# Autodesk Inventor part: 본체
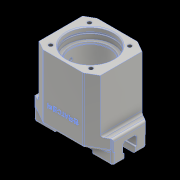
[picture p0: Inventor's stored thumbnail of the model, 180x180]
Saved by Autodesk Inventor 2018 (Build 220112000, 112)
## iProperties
Created: 2023-05
Part Number: 본체
Material: 알루미늄 6061
Document SubType Name: Modeling
Designer: home
Density: 2.7 g/cm^3
Appearance: 알루미늄 - 평지
Mass: 915.939 g
Surface Area: 565.433 cm^2
Volume: 339.237 cm^3
Author: home
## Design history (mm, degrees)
sketch "스케치1"
  geometry: L1 (-26, -35)-(26, -35); L2 (40, -26.917)-(40, 26.917); L3 (26, 35)-(-26, 35); L4 (-40, 26.917)-(-40, -26.917); L5 (-40, -35)-(40, 35); L6 (40, -35)-(-40, 35); L7 (-26, 35)-(-51, 20.566); L8 (26, 35)-(51, 20.566); L9 (-26, -35)-(-51, -20.566); L10 (26, -35)-(51, -20.566); L11 (51, -20)-(51, 20); L12 (-51, -20)-(-51, 20); 5 further points
  constraints: 24 end point, 8 point on line, 6 midpoint, 2 horizontal alignment, 2 parallel, 2 vertical, 1 horizontal, 1 perpendicular
  dimensions: "d0" = 80 distance between parallel lines of L2 L4; "d1" = 70 distance between parallel lines of L1 L3; "d4" = 52 distance of L3.end L3.start; "d5" = 52 distance of L1.end L1.start; "d6" = 26 horizontal distance of L1.start point (0, 0); "d7" = 26 horizontal distance of L3.end point (0, 0); "d8" = 60 deg angle of L7 L9; "d9" = 30 deg angle of L1 L9; "d10" = 60 deg angle of L8 L10; "d11" = 30 deg angle of L1 L10; "d12" = 71.1859 deg angle of L5 L8; "d13" = 11.1859 deg angle of L6 L8; "d14" = 43.31089 distance from line of point (0, 0) L8; "d15" = 40 distance from line of point (0, 0) L2; "d16" = 7 distance from line of L5.end L8; "d17" = 53.62178 distance from line of L6.start L8; "d18" = 33 distance from line of L6.end L8; "d19" = 93.62178 distance from line of L5.start L8; "d120" = 40 distance of L11.start L11.end; "d121" = 40 distance of L12.start L12.end; "d122" = 102 distance between parallel lines of L12 L11; "d123" = 51 distance from line of point (0, 0) L11
extrude "돌출1" new body sketch "스케치1" distance "d20" = 84; taper "d21" = 0 deg
sketch "스케치4"
  geometry: L1 (51, -69)-(-51, -69); L2 (-51, -69)-(-51, -99); L3 (-51, -99)-(51, -99); L4 (51, -99)-(51, -69); L5 (51, -69)-(-51, -99); L6 (-51, -69)-(51, -99); 3 further points
  constraints: 12 end point, 3 midpoint, 2 parallel, 1 horizontal, 1 perpendicular, 1 vertical alignment
  dimensions: "d23" = 102 distance between parallel lines of L2 L4; "d24" = 99 distance from line of point (0, 0) L3; "d25" = 30 distance between parallel lines of L3 L1
extrude "돌출2" join sketch "스케치4" stored distance "d26" = 44; taper "d27" = 0 deg
sketch "스케치5"
  geometry: L1 (-51, -99)-(-51, -69) reference; L2 (-51, -69)-(-40, -69) reference; L3 (-40, -84)-(-40, -69) reference; L4 (40, -84)-(-40, -84) reference; L5 (40, -69)-(40, -84) reference; L6 (40, 0)-(40, -69) reference; L7 (-40, 0)-(40, 0) reference; L8 (-40, -69)-(-40, 0) reference; L9 (51, -99)-(-51, -99) reference; L10 (51, -69)-(51, -99) reference; L11 (40, -69)-(51, -69) reference; L12 (25, -93)-(-25, -93); L13 (-25, -93)-(-25, -99); L14 (-25, -99)-(25, -99); L15 (25, -99)-(25, -93); L16 (25, -93)-(-25, -99); L17 (-25, -93)-(25, -99); 5 further points
  constraints: 12 end point, 6 midpoint, 2 parallel, 1 horizontal, 1 perpendicular, 1 vertical alignment
  dimensions: "d28" = 50 distance between parallel lines of L13 L15; "d29" = 6 distance between parallel lines of L12 L14
extrude "돌출3" cut sketch "스케치5" extent not by distance; stored distance "d30" = 44; taper "d31" = 0 deg
sketch "스케치6"
  geometry: L1 (-30, 44)-(0, 44) reference; L2 (0, 44)-(0, 0) reference; L3 (0, 0)-(-30, 0) reference; L4 (-30, 0)-(-30, 44) reference; L5 (-30, 14.8)-(-9, 14.8); L6 (-9, 14.8)-(-9, 29.2); L7 (-9, 29.2)-(-30, 29.2); L8 (-30, 29.2)-(-30, 14.8); L9 (-30, 14.8)-(-9, 29.2); L10 (-9, 14.8)-(-30, 29.2); L11 (-22, 13)-(-11, 13); L12 (-22, 31)-(-11, 31); L13 (-11, 13)-(-10.483, 14.8); L14 (-11, 31)-(-10.229, 29.2); L15 (-22, 13)-(-22.448, 14.8); L16 (-22, 31)-(-22.215, 29.2); 4 further points
  constraints: 24 end point, 5 midpoint, 4 point on line, 3 horizontal, 2 parallel, 1 horizontal alignment, 1 perpendicular
  dimensions: "d32" = 21 distance of L7.end L6.end; "d33" = 14.4 distance of L6.end L5.end; "d34" = 11 distance of L12.start L12.end; "d35" = 11 distance of L11.start L11.end; "d36" = 8 horizontal distance of L5.start L11.start; "d37" = 8 distance from line of L4 L12.start; "d38" = 18 distance between parallel lines of L12 L11; "d39" = 9 distance from line of point (-19.5, 22) L11; "d46" = 66.8015 deg angle of L3 L14; "d47" = 106.028 deg angle of L3 L13; "d48" = 83.1985 deg angle of L3 L16; "d49" = 103.972 deg angle of L3 L15
  node "절단 모서리 투영2"
extrude "돌출4" cut sketch "스케치6" extent not by distance; stored distance "d50" = 44; taper "d51" = 0 deg
sketch "스케치8"
  geometry: 2 further points
  constraints: 1 coincident
hole "구멍1" sketch "스케치8" at (0, 0) diameter "d53" = 60; stored, may be unused: countersink angle "d57" = 90 deg, drill point angle "d59" = 0 deg; dims "d54" = 6, "d55" = 4, "d56" = 2, "d58" = 14
node "작업 평면3"
sketch "스케치9"
  geometry: C1 r 31.5 at (0, 0); 1 further point
  constraints: 1 centre point, 1 coincident
  dimensions: "d61" = 63 diameter of C1
extrude "돌출5" cut sketch "스케치9" distance "d62" = 2.2; taper "d63" = 0 deg
node "작업 평면4"
sketch "스케치10"
  geometry: C1 r 25 at (0, 0); 1 further point
  constraints: 1 centre point, 1 coincident
  dimensions: "d65" = 50 diameter of C1
extrude "돌출6" cut sketch "스케치10" distance "d66" = 2; taper "d67" = 20 deg
node "작업 평면5"
sketch "스케치11"
  geometry: C1 r 25 at (0, 0); 1 further point
  constraints: 1 centre point, 1 coincident
  dimensions: "d69" = 50 diameter of C1
extrude "돌출7" cut sketch "스케치11" stored distance "d70" = 2; taper "d71" = 0 deg
hole "구멍2" diameter "d74" = 16; stored, may be unused: countersink angle "d78" = 90 deg, drill point angle "d80" = 0 deg; dims "d75" = 6, "d76" = 4, "d77" = 2, "d79" = 14, "d83" = 10, "d84" = 10
node "작업 평면6"
sketch "스케치12"
  geometry: C1 r 31.5 at (51, -22) reference; C2 r 10 at (51, -22); 1 further point
  constraints: 1 centre point, 1 coincident
  dimensions: "d82" = 20 diameter of C2
extrude "돌출8" cut sketch "스케치12" stored distance "d85" = 3.2; taper "d86" = 0 deg
node "작업 평면7"
sketch "스케치15"
  geometry: L1 (26, 25)-(-26, 25); L2 (-26, 25)-(-26, -25); L3 (-26, -25)-(26, -25); L4 (26, -25)-(26, 25); L5 (26, 25)-(-26, -25); L6 (-26, 25)-(26, -25); 5 further points
  constraints: 12 end point, 4 coincident, 2 midpoint, 2 parallel, 1 horizontal, 1 perpendicular
  dimensions: "d96" = 52 distance of L3.end L2.end; "d97" = 50 distance of L2.end L1.end
hole "구멍3" sketch "스케치15" at (26, -25), (26, 25), (-26, 25), (-26, -25) diameter "d98" = 4.917; stored, may be unused: countersink angle "d102" = 90 deg, drill point angle "d104" = 118 deg; dims "d99" = 12, "d100" = 4, "d101" = 2, "d103" = 14
sketch "스케치16"
  geometry: L1 (8, -37)-(42, -37); L2 (42, -37)-(42, -7); L3 (42, -7)-(8, -7); L4 (8, -7)-(8, -37); L5 (8, -37)-(42, -7); L6 (42, -37)-(8, -7); 5 further points
  constraints: 12 end point, 4 coincident, 2 midpoint, 2 parallel, 1 horizontal, 1 perpendicular
  dimensions: "d105" = 34 distance of L3.end L2.end; "d106" = 30 distance of L2.end L1.end
hole "구멍4" sketch "스케치16" at (8, -7), (8, -37), (42, -37), (42, -7) diameter "d107" = 2.459; stored, may be unused: countersink angle "d111" = 90 deg, drill point angle "d113" = 118 deg; dims "d108" = 6, "d109" = 4, "d110" = 2, "d112" = 8
sketch "스케치17"
  geometry: L1 (-26, 35)-(26, 35) reference; L2 (-40, 26.917)-(-26, 35) reference; L3 (-40, -26.917)-(-40, 26.917) reference; L4 (-26, -35)-(-40, -26.917) reference; L5 (26, -35)-(-26, -35) reference; L6 (40, -26.917)-(26, -35) reference; L7 (40, 26.917)-(40, -26.917) reference; L8 (26, 35)-(40, 26.917) reference; L9 (-38, -28.072)-(-38, 28.072); C1 r 2.458 at (-26, 25) reference; C2 r 2.458 at (26, -25) reference; C3 r 2.458 at (26, 25) reference; C4 r 2.458 at (-26, -25) reference; C5 r 30 at (0, 0) reference; 1 further point
  constraints: 2 end point, 2 point on line, 1 vertical
  dimensions: "d114" = 2 distance between parallel lines of L9 L3
extrude "돌출10" cut sketch "스케치17" distance "d115" = 64; taper "d116" = 0 deg
sketch "스케치22"
  geometry: L1 (-51, -9)-(51, -9) reference; L2 (51, -9)-(51, -22) reference; L3 (51, -22)-(40, -22) reference; L4 (40, -22)-(40, -26.917) reference; L5 (40, -26.917)-(26, -35) reference; L6 (26, -35)-(-26, -35) reference; L7 (-26, -35)-(-40, -26.917) reference; L8 (-40, -26.917)-(-40, -22) reference; L9 (40, -22)-(-40, -22) reference; L10 (-51, -22)-(-51, -9) reference; L11 (-40, -22)-(-51, -22) reference; L12 (-51, 22)-(-40, 22) reference; L13 (-40, 22)-(40, 22) reference; L14 (40, 26.917)-(40, 22) reference; L15 (26, 35)-(40, 26.917) reference; L16 (-26, 35)-(26, 35) reference; L17 (-40, 26.917)-(-26, 35) reference; L18 (-40, 22)-(-40, 26.917) reference; L19 (-51, 9)-(-51, 22) reference; L20 (51, 9)-(-51, 9) reference; L21 (51, 22)-(51, 9) reference; L22 (40, 22)-(51, 22) reference; L23 (-26, 35)-(-51, 20.566); L24 (-26, -35)-(26, -35) reference; L25 (-26, -35)-(-51, -20.566); L26 (26, -35)-(51, -20.566); L27 (26, 35)-(51, 20.566); L28 (-26, -35)-(-26, 35); L29 (26, -35)-(38, -28.072) reference; L30 (26, -35)-(26, 35); L31 (-51, -20.566)-(-51, 20.566); L32 (51, -20.566)-(51, 20.566); 1 further point
  constraints: 16 end point, 5 point on line, 2 parallel, 1 vertical
  dimensions: "d152" = 30 deg angle of L24 L25; "d153" = 30 deg angle of L6 L26; "d154" = 30 deg angle of L16 L27; "d155" = 30 deg angle of L16 L23
extrude "돌출12" join sketch "스케치22" stored distance "d156" = 64; taper "d157" = 0 deg
sketch "스케치14"
  geometry: L1 (-29, 0)-(29, 0); L2 (-29, -6)-(29, -6); L3 (29, 6)-(-29, 6); C1 r 12 at (0, 0); A1 r 6 centre (-29, 0) between (-29, 6) and (-29, -6); A2 r 6 centre (29, 0) between (29, -6) and (29, 6); 2 further points
  constraints: 8 end point, 4 point on circle, 4 tangent, 3 centre point, 2 coincident, 1 horizontal, 1 horizontal alignment, 1 midpoint, 1 parallel
  dimensions: "d91" = 24 diameter of C1; "d92" = 12 distance between parallel lines of L3 L2; "d93" = 58 distance of L1.start L1.end
extrude "돌출9" cut sketch "스케치14" distance "d94" = 30; taper "d95" = 0 deg
sketch "스케치23"
  geometry: L1 (41.028, -68.033)-(10.972, -68.033); L2 (10.972, -68.033)-(10.972, -49.967); L3 (10.972, -49.967)-(41.028, -49.967); L4 (41.028, -49.967)-(41.028, -68.033); L5 (-25, -99)-(1, -99) reference; 3 further points
  constraints: 2 midpoint, 1 parallel, 1 vertical alignment, 2 other
  dimensions: "d158" = 40 distance from line of L5 point (10.972, -59); "d159" = 49.03303 distance between parallel lines of L3 L5; "d160" = 30.05535 distance between parallel lines of L4 L2
feature "엠보싱1" sketch "스케치23" dims "d161" = 0.5, "d162" = 0
fillet "모깎기7" dims "d168" = 3
fillet "모깎기8" dims "d169" = 3
fillet "모깎기9" dims "d170" = 3
fillet "모깎기10" dims "d171" = 3
fillet "모깎기11" dims "d172" = 3
fillet "모깎기12" dims "d173" = 3
sketch "스케치24"
  geometry: L1 (0, 56.144)-(0, 0) reference; 5 further points
  constraints: 2 horizontal alignment, 2 midpoint
  dimensions: "d174" = 28 distance from line of L1 point (-28, 28.072); "d175" = 28 distance of point (-28, 28.072) point (-56, 28.072)
chamfer "모따기1" distance "d176" = 1; stored, may be unused: second distance "d177" = 2, angle "d178" = 45 deg
fillet "모깎기13" dims "d179" = 2
fillet "모깎기14" dims "d180" = 0.4
chamfer "모따기2" distance "d181" = 1; stored, may be unused: second distance "d182" = 2, angle "d183" = 45 deg
chamfer "모따기3" distance "d184" = 1; stored, may be unused: second distance "d185" = 2, angle "d186" = 45 deg
extrude "돌출13" cut sketch "스케치6" extent not by distance; stored distance "d187" = 10; taper "d188" = 0 deg
hole "구멍5" sketch "스케치24" diameter "d189" = 8; stored, may be unused: countersink angle "d195" = 90 deg, drill point angle "d197" = 118 deg; dims "d190" = 7.4, "d191" = 0.62479, "d192" = 7.985, "d193" = 4, "d194" = 2, "d196" = 11
sketch "스케치25"
  geometry: C1 r 4.224 at (-28, 28.072) reference; C2 r 4.224 at (-56, 28.072) reference; C3 r 2 at (-56, 28.072); C4 r 2 at (-28, 28.072); 1 further point
  constraints: 2 centre point, 2 coincident
  dimensions: "d198" = 4 diameter of C3; "d199" = 4 diameter of C4
extrude "돌출14" cut sketch "스케치25" distance "d200" = 20; taper "d201" = 0 deg
fillet "모깎기15" dims "d202" = 3
node "솔리드1"
node "투영된 루프1"
node "절단 모서리 투영1"
node "절단 모서리 투영3"
other parameters: "d40" = 30 deg, "d41" = 30 deg, "d60" = 6, "d64" = -2, "d68" = -45, "d81" = -35, "d90" = -99
